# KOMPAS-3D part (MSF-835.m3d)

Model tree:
1. Ось X
2. Ось Y
3. Ось Z
4. Начало координат  (labels: Операция без истории:1)

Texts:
  Линия-выноска #1
  Линия-выноска #2
  Линия-выноска #3
  Отклонения формы и база
  Марка координационной оси
  Марка/позиционное обозначение с линией-выноской
  Марка/позиционное обозначение на линии
  Марка/позиционное обозначение без линии-выноски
